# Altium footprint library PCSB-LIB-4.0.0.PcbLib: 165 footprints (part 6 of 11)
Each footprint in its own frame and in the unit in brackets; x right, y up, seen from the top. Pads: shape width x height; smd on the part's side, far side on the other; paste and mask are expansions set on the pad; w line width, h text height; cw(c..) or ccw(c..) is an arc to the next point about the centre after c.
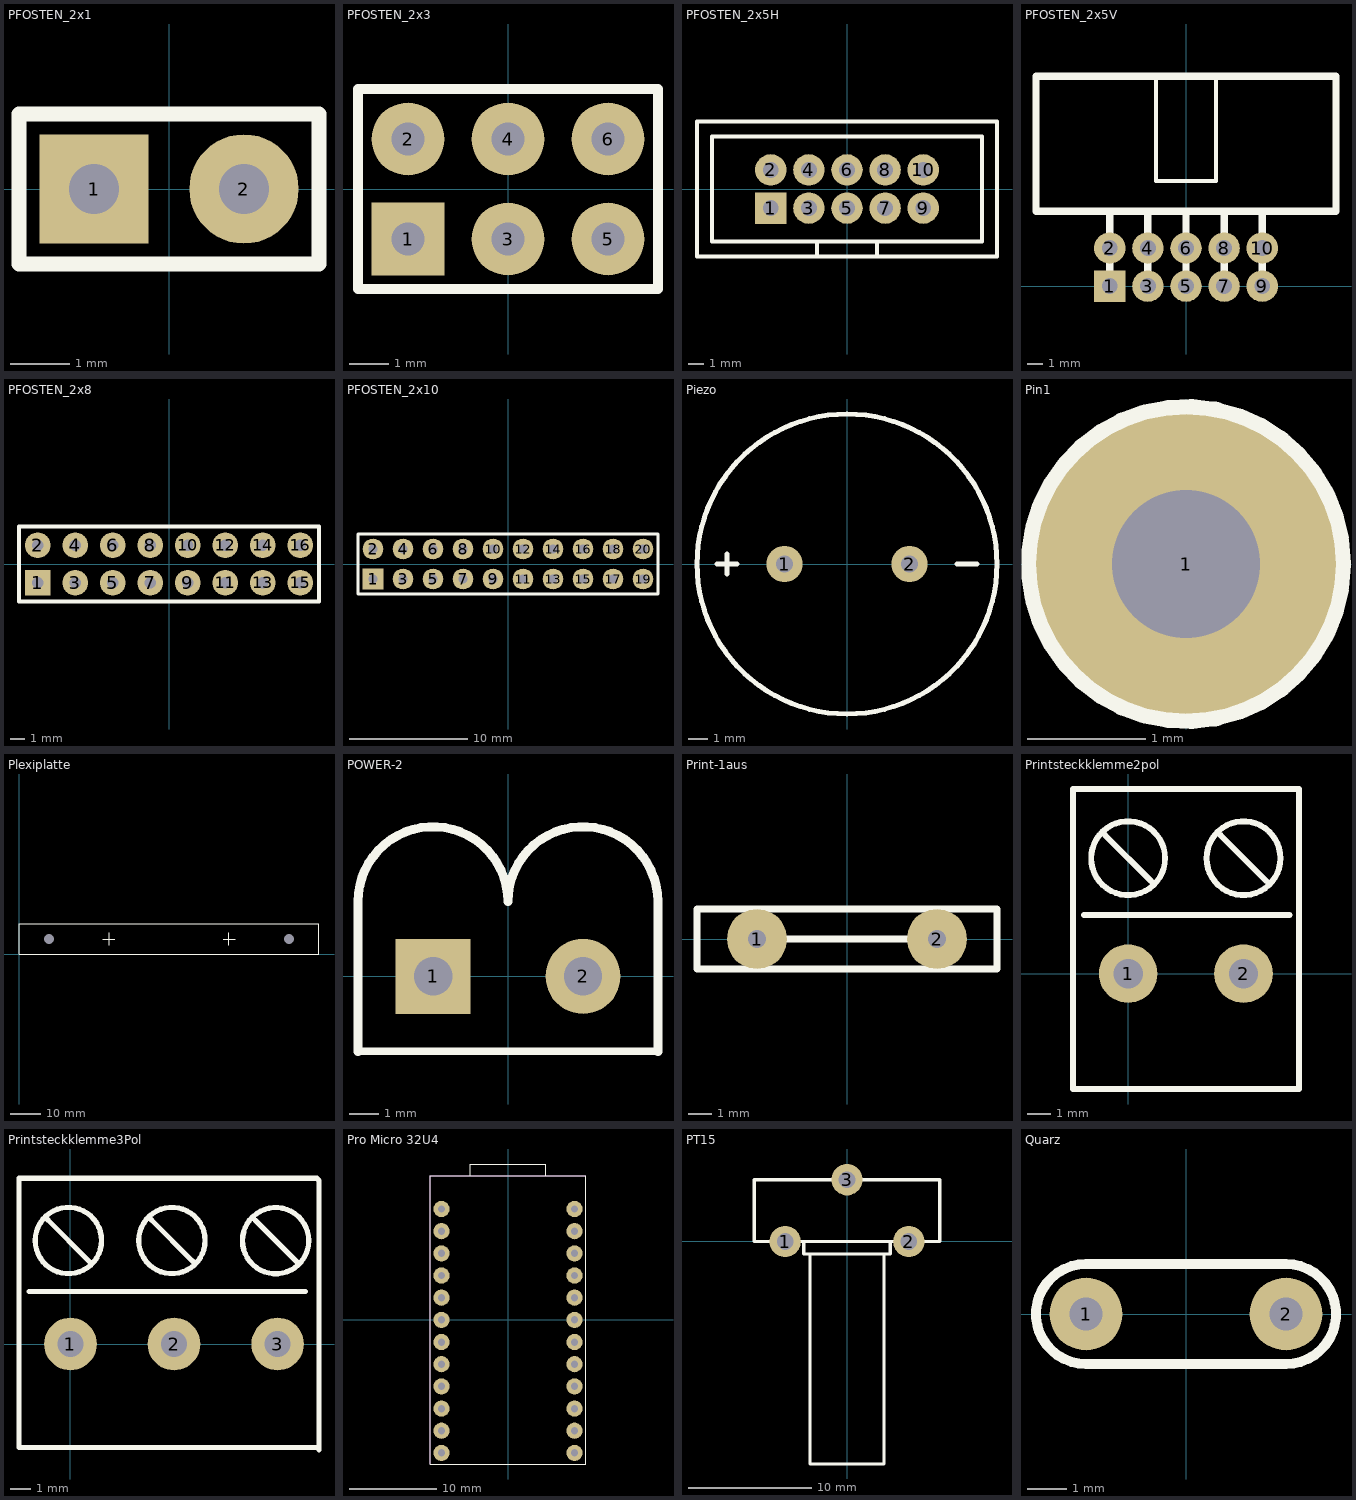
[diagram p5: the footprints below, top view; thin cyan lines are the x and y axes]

## PFOSTEN_2x1 [mm]
pads (2):
  rect 1.85x1.85 hole 0.85 mask+0.102: 1(-1.27,0)
  round 1.85 hole 0.85 mask+0.102: 2(1.27,0)
Top Overlay:
  lines w0.254: -2.54,-1.27 2.54,-1.27 2.54,1.27 -2.54,1.27 -2.54,-1.27

## PFOSTEN_2x3 [mm]
pads (6):
  rect 1.85x1.85 hole 0.85 mask+0.102: 1(-2.54,-1.27)
  round 1.85 hole 0.85 mask+0.102: 2(-2.54,1.27) 3(0,-1.27) 4(0,1.27) 5(2.54,-1.27) 6(2.54,1.27)
Top Overlay:
  lines w0.254: -3.81,-2.54 -3.81,2.54 3.81,2.54 3.81,-2.54 -3.81,-2.54

## PFOSTEN_2x5H [mm]
height 9
pads (10):
  rect 2.1x2.1 hole 1.05 mask+0.102: 1(-5.08,-1.27)
  round 2.1 hole 1.05 mask+0.102: 2(-5.08,1.27) 3(-2.54,-1.27) 4(-2.54,1.27) 5(0,-1.27) 6(0,1.27) 7(2.54,-1.27) 8(2.54,1.27) 9(5.08,-1.27) 10(5.08,1.27)
Top Overlay:
  lines w0.254: -2,-4.5 -2,-3.5 ; -0.5,4.5 10,4.5 10,-4.5 -10,-4.5 -10,4.5 0,4.5 ; 2,-4.5 2,-3.5 ; -9,-3.5 9,-3.5 9,3.5 -9,3.5 -9,-3.5

## PFOSTEN_2x5V [mm]
height 9
pads (10):
  rect 2.1x2.1 hole 1.05 mask+0.102: 1(-5.08,0)
  round 2.1 hole 1.05 mask+0.102: 2(-5.08,2.54) 3(-2.54,0) 4(-2.54,2.54) 5(0,0) 6(0,2.54) 7(2.54,0) 8(2.54,2.54) 9(5.08,0) 10(5.08,2.54)
Top Overlay:
  lines w0.254: -2,14 -2,7 2,7 2,14
  lines w0.5: -5.08,0 -5.08,5 ; -2.54,0 -2.54,5 ; 0,0 0,5 ; 2.54,0 2.54,5 ; 5.08,0 5.08,5 ; 0,5 -10,5 -10,14 10,14 10,5 0,5

## PFOSTEN_2x8 [mm]
pads (16):
  rect 1.75x1.75 hole 0.75: 1(-8.89,-1.27)
  round 1.75 hole 0.75: 2(-8.89,1.27) 3(-6.35,-1.27) 4(-6.35,1.27) 5(-3.81,-1.27) 6(-3.81,1.27) 7(-1.27,-1.27) 8(-1.27,1.27) 9(1.27,-1.27) 10(1.27,1.27) 11(3.81,-1.27) 12(3.81,1.27) 13(6.35,-1.27) 14(6.35,1.27) 15(8.89,-1.27) 16(8.89,1.27)
Top Overlay:
  lines w0.254: -10.16,-2.54 -10.16,2.54 10.16,2.54 10.16,-2.54 -10.16,-2.54

## PFOSTEN_2x10 [mm]
pads (20):
  rect 1.75x1.75 hole 0.75: 1(-11.43,-1.27)
  round 1.75 hole 0.75: 2(-11.43,1.27) 3(-8.89,-1.27) 4(-8.89,1.27) 5(-6.35,-1.27) 6(-6.35,1.27) 7(-3.81,-1.27) 8(-3.81,1.27) 9(-1.27,-1.27) 10(-1.27,1.27) 11(1.27,-1.27) 12(1.27,1.27) 13(3.81,-1.27) 14(3.81,1.27) 15(6.35,-1.27) 16(6.35,1.27) 17(8.89,-1.27) 18(8.89,1.27) 19(11.43,-1.27) 20(11.43,1.27)
Top Overlay:
  lines w0.254: -12.7,-2.54 -12.7,2.54 12.7,2.54 12.7,-2.54 -12.7,-2.54

## Piezo [mm]
pads (2):
  round 1.85 hole 0.85: 1(-3.175,0) 2(3.175,0)
Top Overlay:
  circle w0.254: c0,0 r7.62
  lines w0.254: -6.604,0 -5.588,0 ; -6.096,-0.508 -6.096,0.508 ; 5.588,0 6.604,0

## Pin1 [mm]
pads (1):
  round 2.54 hole 1.25: 1(0,0)
Top Overlay:
  circle w0.254: c0,0 r1.27

## Plexiplatte [mm]
height 60
pads (2):
  round 1.524 hole 3.2 unplated: 0(10,5) 0(90,5)
Top Overlay:
  lines w0.1: 28,5 32,5 ; 30,3 30,7 ; 68,5 72,5 ; 70,3 70,7
  lines w0.3: 0,0 0,10 100,10 100,0 0,0

## POWER-2 [mm]
pads (2):
  rect 2.54x2.54 hole 1.3: 1(-2.54,0)
  round 2.54 hole 1.3: 2(2.54,0)
Top Overlay:
  lines w0.254: -5.08,-2.54 5.08,-2.54
  lines w0.305: -5.08,-2.54 -5.085,2.531 cw(c-2.545,2.531) -0.005,2.531 cw(c2.535,2.531) 5.075,2.531 5.08,-2.54

## Print-1aus [mm]
height 8
pads (2):
  round 2.54 hole 0.75: 1(-3.81,0) 2(3.81,0)
Top Overlay:
  lines w0.3: -3.81,0 3.81,0 ; -6.35,-1.27 -6.35,1.27 0,1.27 6.35,1.27 6.35,-1.27 -6.35,-1.27

## Printsteckklemme2pol [mm] "Bestellbar bei RS Nr. 897-1297"
pads (2):
  round 2.54 hole 1.27: 1(0,0) 2(5,0)
Top Overlay:
  circle w0.254: c0,5 r1.601
  circle w0.254: c5,5 r1.601
  lines w0.1: 6,3.75 6,4
  lines w0.254: -1.905,2.54 6.985,2.54 ; -1,6 1,4 ; 4,6 6,4 ; 7.385,-5 -2.385,-5 -2.385,8 7.385,8 ; 7.4,-5 7.4,8

## Printsteckklemme3Pol [mm]
pads (3):
  round 2.54 hole 1.27: 1(0,0) 2(5,0) 3(10,0)
Top Overlay:
  circle w0.254: c-0.1,5 r1.601
  circle w0.254: c4.9,5 r1.601
  circle w0.254: c9.907,4.993 r1.601
  lines w0.1: 5.9,3.75 5.9,4 ; 10.907,3.743 10.907,3.993
  lines w0.254: -2.005,2.54 6.885,2.54 11.34,2.54 ; -1.1,6 0.9,4 ; 3.9,6 5.9,4 ; 8.907,5.993 10.907,3.993 ; 11.9,-5 7.285,-5 -2.485,-5 -2.485,8 7.285,8 11.9,8 12,7.9 12,-5.1

## Pro Micro 32U4 [mm]
pads (24):
  round 1.85 hole 0.85 mask+0.05: J3_1(-7.62,-15.24) J3_2(-7.62,-12.7) J3_3(-7.62,-10.16) J3_4(-7.62,-7.62) J3_5(-7.62,-5.08) J3_6(-7.62,-2.54) J3_7(-7.62,0) J3_8(-7.62,2.54) J3_9(-7.62,5.08) J3_10(-7.62,7.62) J3_11(-7.62,10.16) J3_12(-7.62,12.7) J4_1(7.62,12.7) J4_2(7.62,10.16) J4_3(7.62,7.62) J4_4(7.62,5.08) J4_5(7.62,2.54) J4_6(7.62,0) J4_7(7.62,-2.54) J4_8(7.62,-5.08) J4_9(7.62,-7.62) J4_10(7.62,-10.16) J4_11(7.62,-12.7) J4_12(7.62,-15.24)
Top Overlay:
  lines w0.127: -4.32,16.51 -4.32,17.855 4.32,17.855 4.32,16.51 ; -8.89,-16.51 8.89,-16.51 8.89,16.51 -8.89,16.51 -8.89,-16.51
Mechanical 13:
  lines w0.127: -8.89,-16.51 8.89,-16.51 8.89,16.51 4.32,16.51 -4.32,16.51 -8.89,16.51 -8.89,-16.51

## PT15 [mm]
pads (3):
  round 2.54 hole 1.35: 1(-5.006,-0.011) 2(4.994,-0.011) 3(-0.006,4.989)
Top Overlay:
  lines w0.254: -3.506,-0.011 -3.506,-1.011 3.494,-1.011 3.494,-0.011 ; -3,-1.011 -3,-18 3,-18 3,-1.011 ; -7.506,-0.011 7.494,-0.011 7.494,4.989 -7.506,4.989 -7.506,-0.011

## Quarz [mm]
pads (2):
  round 1.85 hole 0.85: 1(-2.54,0) 2(2.54,0)
Top Overlay:
  lines w0.254: -2.54,-1.27 cw(c-2.54,0) -2.54,1.27 2.54,1.27 cw(c2.54,0) 2.54,-1.27 -2.54,-1.27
